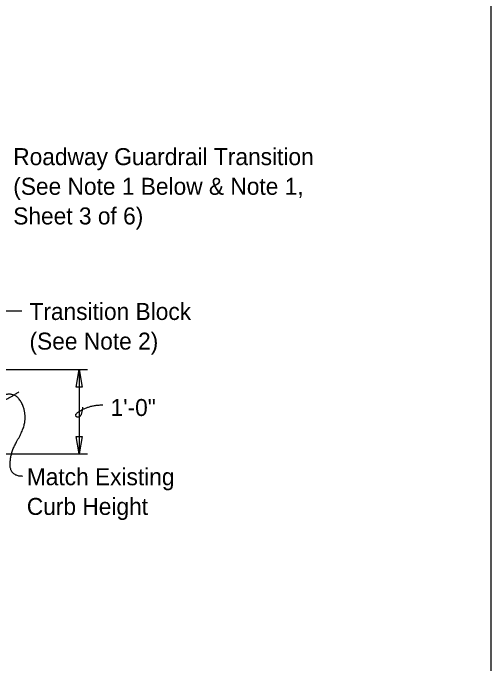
# Model space of a CAD drawing. Extents: x 1.5 to 68.7, y 0 to 31.
# Drawn here: x 36.86 to 42.53, y 9.19 to 16.91 of the extents above; entities that cross this region are included whole.
import ezdxf

# ---------------------------------------------------------------- set-up
doc = ezdxf.new("R2010")
doc.units = 0
for name, color, linetype in [('ActivePts-ConstElements', 7, 'Continuous'), ('AdhocPoint_dp', 7, 'Continuous'), ('TextMisc', 7, 'Continuous')]:
    doc.layers.add(name, color=color, linetype=linetype)

# ---------------------------------------------------------------- blocks, each defined once
blk = doc.blocks.new('Terminator-Arrow')
at = {"layer": 'AdhocPoint_dp'}
blk.add_lwpolyline([(0, 0), (-0.00041, 0.000069), (-0.00041, -0.000069)], close=True, dxfattribs=at)

msp = doc.modelspace()

# ---------------------------------------------------------------- linework, layer by layer
at = {"layer": 'ActivePts-ConstElements'}
msp.add_lwpolyline([(1.4667, 28.1828), (42.5333, 28.1828), (42.5333, 1.7828), (1.4667, 1.7828)], close=True, dxfattribs=at)
at = {"layer": 'AdhocPoint_dp'}
for p, q in [((34.7705, 12.682), (37.7448, 12.682)), ((37.6451, 12.6821), (37.6451, 11.6821)), ((34.7705, 11.682), (37.7448, 11.682))]:
    msp.add_line(p, q, dxfattribs=at)
for points in [[(36.9638, 13.3766), (36.3023, 13.3835), (36.0282, 13.2463), (35.8452, 13.0751), (35.6496, 12.7777), (35.6496, 12.4881), (35.1021, 12.2847), (34.6328, 12.2768)], [(36.9767, 11.4144), (36.8259, 11.4144), (36.8259, 11.6957), (37.0041, 11.9975), (37.0041, 12.217), (36.9013, 12.3885), (36.7299, 12.3885), (36.6545, 12.3062), (36.7573, 12.3062), (36.9287, 12.416)], [(37.6866, 12.2346), (37.6705, 12.0931), (37.5692, 12.1451), (37.7866, 12.2625), (37.9279, 12.2625)]]:
    msp.add_open_spline(points, degree=2, dxfattribs=at)

# ---------------------------------------------------------------- block references
at = {"layer": 'AdhocPoint_dp', "xscale": 506.349, "yscale": -512.1577380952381}
for p, rotation in [((37.6445, 12.6818), 90), ((37.6445, 11.6817), -90)]:
    msp.add_blockref('Terminator-Arrow', p, dxfattribs=dict(at, rotation=rotation))

# ---------------------------------------------------------------- texts
at = {"layer": 'AdhocPoint_dp'}
for s, p in [('Roadway Guardrail Transition', (36.8631, 15.1086)), ('(See Note 1 Below & Note 1,', (36.8631, 14.7566)), ('Sheet 3 of 6)', (36.8631, 14.4046)), ('Transition Block', (37.0561, 13.2708)), ('(See Note 2)', (37.0561, 12.9188)), ('Match Existing ', (37.0243, 11.3085)), ('Curb Height', (37.0243, 10.9565))]:
    msp.add_text(s, height=0.2016, dxfattribs=at).set_placement(p)
at = {"layer": 'TextMisc'}
msp.add_text('1\'-0"', height=0.2016, dxfattribs=at).set_placement((38.0185, 12.1308))

doc.saveas('drawing.dxf')
